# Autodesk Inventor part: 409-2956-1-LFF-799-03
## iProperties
Created: 2010-11
Part Number: 409-2956-1-LFF-799-03
Material: 3/4" OD TUBE - SS
Document SubType Name: Modeling
Designer: S. Boerckel
Engineer: Steve Boerckel
Mass: 309.983 g
Surface Area: 466.545 cm^2
Volume: 38.3643 cm^3
Density: 8.08 g/cm^3
Description: DRAIN TUBING
Length: 11.124 in
Author: S. Boerckel
Revision Number: 0
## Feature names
1. Sweep1
